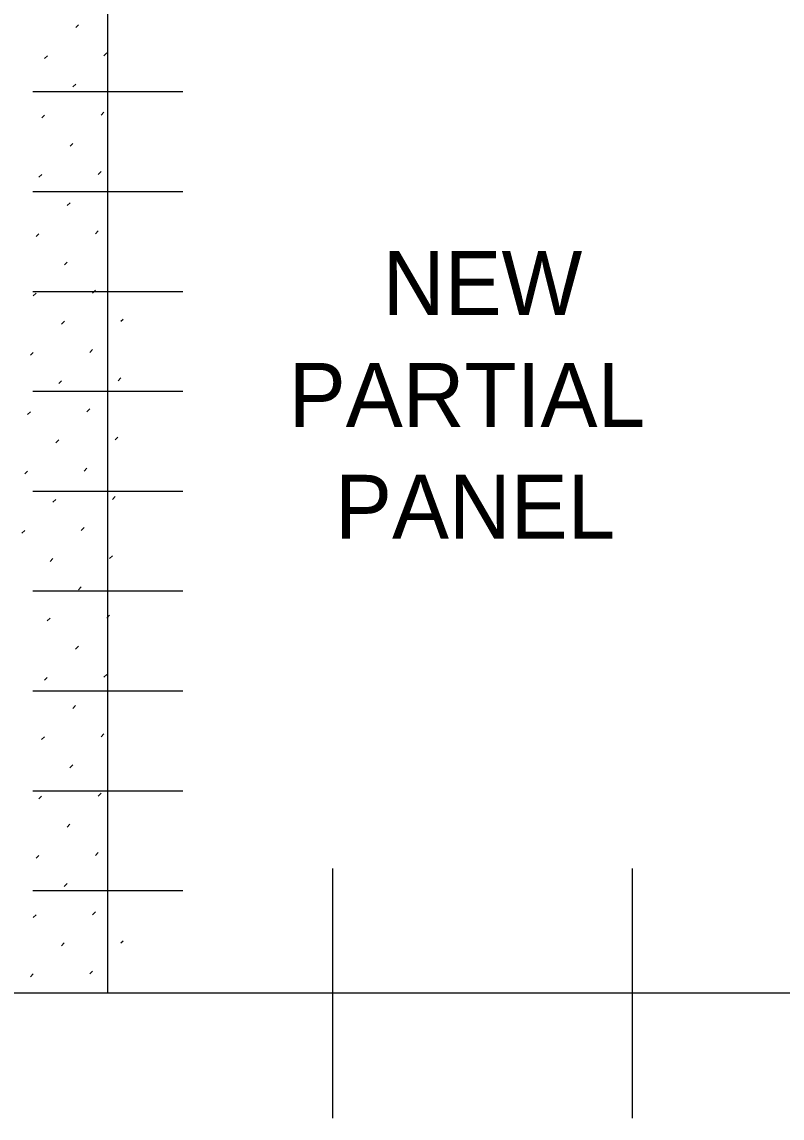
# Model space of a CAD drawing. Extents: x 49991.4 to 50021, y 49987.6 to 50011.4.
# Drawn here: x 50010.64 to 50011.591, y 49996.135 to 49997.507 of the extents above; entities that cross this region are included whole.
import ezdxf

# ---------------------------------------------------------------- set-up
doc = ezdxf.new("R2010")
doc.units = 0
for name, color, linetype in [('Level 1', 7, 'Continuous'), ('Level 10', 7, 'Continuous'), ('Level 2', 7, 'Continuous'), ('Level 4', 7, 'Continuous')]:
    doc.layers.add(name, color=color, linetype=linetype)

msp = doc.modelspace()

# ---------------------------------------------------------------- linework, layer by layer
at = {"layer": 'Level 1'}
for p, q in [((50010.7473, 49996.2915), (50010.7473, 49997.7903)), ((50011.6848, 49996.2915), (50009.8098, 49996.2915))]:
    msp.add_line(p, q, dxfattribs=at)
at = {"layer": 'Level 10'}
for p, q in [((50010.707, 49997.5001), (50010.7105, 49997.5036)), ((50010.6681, 49997.4612), (50010.6716, 49997.4647)), ((50010.7423, 49997.4647), (50010.7458, 49997.4683)), ((50010.7034, 49997.4258), (50010.707, 49997.4294)), ((50010.6645, 49997.3869), (50010.6681, 49997.3905)), ((50010.7388, 49997.3905), (50010.7423, 49997.394)), ((50010.6999, 49997.3516), (50010.7034, 49997.3551)), ((50010.7352, 49997.3162), (50010.7388, 49997.3198)), ((50010.661, 49997.3127), (50010.6645, 49997.3162)), ((50010.6963, 49997.2773), (50010.6999, 49997.2809)), ((50010.6574, 49997.2384), (50010.661, 49997.242)), ((50010.7317, 49997.242), (50010.7352, 49997.2455)), ((50010.6928, 49997.2031), (50010.6963, 49997.2066)), ((50010.6539, 49997.1642), (50010.6574, 49997.1677)), ((50010.7281, 49997.1677), (50010.7317, 49997.1713)), ((50010.6892, 49997.1288), (50010.6928, 49997.1324)), ((50010.7635, 49997.1324), (50010.7663, 49997.1351)), ((50010.6503, 49997.0899), (50010.6539, 49997.0935)), ((50010.7246, 49997.0935), (50010.7281, 49997.097)), ((50010.6857, 49997.0546), (50010.6892, 49997.0581)), ((50010.76, 49997.0581), (50010.7635, 49997.0617)), ((50010.6468, 49997.0157), (50010.6503, 49997.0192)), ((50010.7211, 49997.0192), (50010.7246, 49997.0228)), ((50010.6822, 49996.9803), (50010.6857, 49996.9839)), ((50010.7564, 49996.9839), (50010.7599, 49996.9874)), ((50010.7175, 49996.945), (50010.7211, 49996.9485)), ((50010.6433, 49996.9414), (50010.6468, 49996.945)), ((50010.6786, 49996.9061), (50010.6822, 49996.9096)), ((50010.7529, 49996.9096), (50010.7564, 49996.9131)), ((50010.6397, 49996.8672), (50010.6433, 49996.8707)), ((50010.714, 49996.8707), (50010.7175, 49996.8742)), ((50010.7493, 49996.8354), (50010.7529, 49996.8389)), ((50010.6751, 49996.8318), (50010.6786, 49996.8354)), ((50010.7104, 49996.7965), (50010.714, 49996.8)), ((50010.6715, 49996.7576), (50010.6751, 49996.7611)), ((50010.7458, 49996.7611), (50010.7493, 49996.7646)), ((50010.7069, 49996.7222), (50010.7104, 49996.7257)), ((50010.7422, 49996.6869), (50010.7458, 49996.6904)), ((50010.668, 49996.6833), (50010.6715, 49996.6868)), ((50010.7033, 49996.648), (50010.7069, 49996.6515)), ((50010.6644, 49996.6091), (50010.668, 49996.6126)), ((50010.7387, 49996.6126), (50010.7422, 49996.6161)), ((50010.6998, 49996.5737), (50010.7033, 49996.5772)), ((50010.6609, 49996.5348), (50010.6644, 49996.5383)), ((50010.7352, 49996.5383), (50010.7387, 49996.5419)), ((50010.6963, 49996.4994), (50010.6998, 49996.503)), ((50010.6574, 49996.4605), (50010.6609, 49996.4641)), ((50010.7316, 49996.4641), (50010.7351, 49996.4676)), ((50010.6927, 49996.4252), (50010.6963, 49996.4287)), ((50010.6538, 49996.3863), (50010.6574, 49996.3898)), ((50010.7281, 49996.3898), (50010.7316, 49996.3934)), ((50010.6892, 49996.3509), (50010.6927, 49996.3545)), ((50010.7634, 49996.3545), (50010.7663, 49996.3573)), ((50010.7245, 49996.3156), (50010.7281, 49996.3191)), ((50010.6503, 49996.312), (50010.6538, 49996.3156))]:
    msp.add_line(p, q, dxfattribs=at)
at = {"layer": 'Level 4'}
for p, q in [((50010.841, 49997.4195), (50010.6535, 49997.4195)), ((50010.841, 49997.2945), (50010.6535, 49997.2945)), ((50010.841, 49997.1695), (50010.6535, 49997.1695)), ((50010.841, 49997.0445), (50010.6535, 49997.0445)), ((50010.841, 49996.9195), (50010.6535, 49996.9195)), ((50010.841, 49996.7945), (50010.6535, 49996.7945)), ((50010.841, 49996.6695), (50010.6535, 49996.6695)), ((50010.841, 49996.5445), (50010.6535, 49996.5445)), ((50011.0285, 49996.4478), (50011.0285, 49996.1353)), ((50011.4035, 49996.4478), (50011.4035, 49996.1353)), ((50010.841, 49996.4195), (50010.6535, 49996.4195))]:
    msp.add_line(p, q, dxfattribs=at)

# ---------------------------------------------------------------- texts
at = {"layer": 'Level 2'}
for s, p in [('NEW', (50011.0913, 49997.1403)), ('PARTIAL ', (50010.9736, 49997.0003)), ('PANEL', (50011.0315, 49996.8603))]:
    msp.add_text(s, height=0.08, dxfattribs=at).set_placement(p)

doc.saveas('drawing.dxf')
